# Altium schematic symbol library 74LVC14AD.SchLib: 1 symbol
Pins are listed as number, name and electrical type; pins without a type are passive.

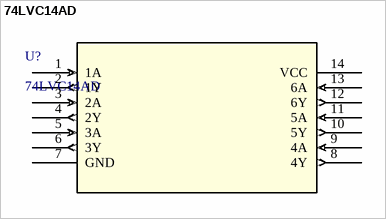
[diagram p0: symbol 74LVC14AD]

## 74LVC14AD
designator U?
Description; Manufacturer_Name: NXP
footprint SOT108-1_NXP
pins: 1 1A (in), 2 1Y (out), 3 2A (in), 4 2Y (out), 5 3A (in), 6 3Y (out), 7 GND (power), 8 4Y (out), 9 4A (in), 10 5Y (out), 11 5A (in), 12 6Y (out), 13 6A (in), 14 VCC (power)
